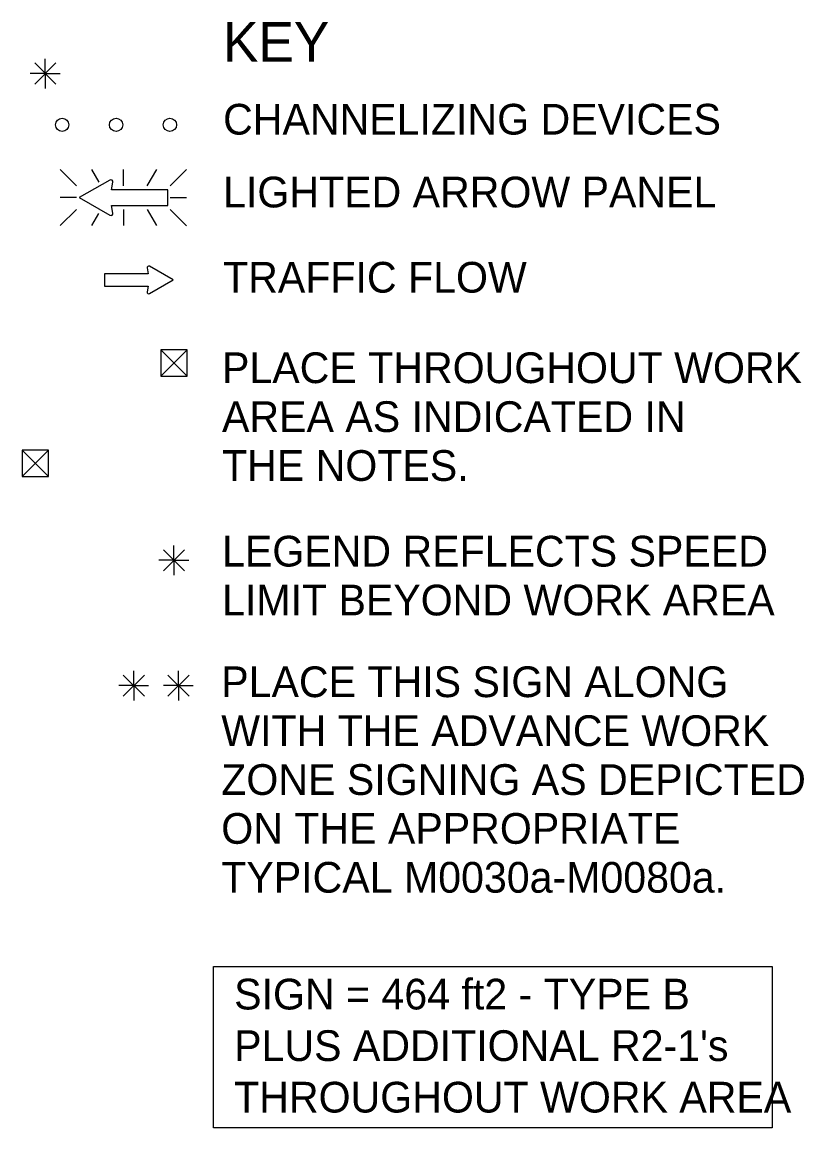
# Model space of a CAD drawing. Extents: x 16480 to 18482, y 7002 to 8333.
# Drawn here: x 17187.3 to 17423.8, y 7874.7 to 8209.5 of the extents above; entities that cross this region are included whole.
import ezdxf

# ---------------------------------------------------------------- set-up
doc = ezdxf.new("R2010")
doc.units = 0
for name, color, linetype in [('MT_SCRATCH_LEVEL_E', 7, 'Continuous'), ('TRAFFIC_SIGNS_PR', 7, 'Continuous'), ('TYPICAL_TEXT_DIMEN_EX', 7, 'Continuous'), ('TYPICAL_TEXT_DIMEN_PR', 7, 'Continuous')]:
    doc.layers.add(name, color=color, linetype=linetype)

msp = doc.modelspace()

# ---------------------------------------------------------------- linework, layer by layer
at = {"layer": 'MT_SCRATCH_LEVEL_E'}
for p, q in [((17225.12, 8135.05), (17225.43, 8133.27)), ((17233.04, 8131.42), (17225.8, 8135.53)), ((17225.43, 8133.27), (17212.17, 8133.27)), ((17212.17, 8133.27), (17212.17, 8129.53)), ((17212.17, 8129.53), (17225.43, 8129.53)), ((17225.43, 8129.53), (17225.12, 8127.75)), ((17225.8, 8127.28), (17233.04, 8131.42))]:
    msp.add_line(p, q, dxfattribs=at)
for centre, start, end in [((17225.58, 8135.13), 60.4248, 189.9638), ((17225.58, 8127.69), 170.0362, 299.7731)]:
    msp.add_arc(centre, 0.463, start, end, dxfattribs=at)
at = {"layer": 'TRAFFIC_SIGNS_PR'}
for p, q in [((17198.85, 8164.8), (17203.79, 8159.87)), ((17210.62, 8160.98), (17208.41, 8164.81)), ((17217.94, 8159.87), (17217.94, 8164.81)), ((17225.17, 8159.87), (17228.02, 8164.81)), ((17232.08, 8159.87), (17237.02, 8164.81)), ((17203.79, 8156.32), (17198.85, 8156.32)), ((17232.08, 8156.32), (17237.02, 8156.32)), ((17198.85, 8147.83), (17203.79, 8152.76)), ((17217.94, 8152.76), (17217.94, 8147.83)), ((17228.06, 8147.83), (17225.22, 8152.76)), ((17232.08, 8152.76), (17237.02, 8147.82)), ((17208.36, 8147.83), (17210.48, 8151.49))]:
    msp.add_line(p, q, dxfattribs=at)
for points in [[(17213.86, 8161.59), (17204.57, 8156.32), (17213.87, 8150.99)], [(17214.74, 8151.62), (17214.34, 8153.89), (17231.35, 8153.89), (17231.35, 8158.69), (17214.34, 8158.69), (17214.74, 8160.97)]]:
    msp.add_lwpolyline(points, dxfattribs=at)
for centre in [(17199.42, 8178.35), (17215.72, 8178.35), (17232.02, 8178.35)]:
    msp.add_circle(centre, 2, dxfattribs=at)
for centre, radius, start, end in [((17214.15, 8161.07), 0.598, 350.7308, 118.8916), ((17214.15, 8151.52), 0.597, 241.4833, 9.9593)]:
    msp.add_arc(centre, radius, start, end, dxfattribs=at)
at = {"layer": 'TYPICAL_TEXT_DIMEN_EX'}
msp.add_lwpolyline([(17245.22, 7923.51), (17414.22, 7923.51), (17414.22, 7874.68), (17245.22, 7874.68)], close=True, dxfattribs=at)
at = {"layer": 'TYPICAL_TEXT_DIMEN_PR'}
for p, q in [((17191.11, 8197.08), (17197.49, 8190.7)), ((17197.49, 8197.08), (17191.11, 8190.7)), ((17194.3, 8193.89), (17194.3, 8198.35)), ((17194.3, 8193.89), (17189.77, 8193.89)), ((17194.3, 8193.89), (17197.49, 8193.89)), ((17194.3, 8193.89), (17198.78, 8193.89)), ((17194.3, 8193.89), (17194.3, 8189.39)), ((17229.27, 8110.26), (17237.27, 8102.26)), ((17229.27, 8102.26), (17237.27, 8110.26)), ((17187.29, 8079.87), (17195.29, 8071.87)), ((17187.29, 8071.87), (17195.29, 8079.87)), ((17230.05, 8049.72), (17236.42, 8043.34)), ((17236.42, 8049.72), (17230.05, 8043.34)), ((17233.23, 8046.53), (17233.23, 8050.99)), ((17233.23, 8046.53), (17228.7, 8046.53)), ((17233.23, 8046.53), (17236.42, 8046.53)), ((17233.23, 8046.53), (17237.71, 8046.53)), ((17233.23, 8046.53), (17233.23, 8042.03)), ((17217.91, 8011.77), (17224.28, 8005.4)), ((17224.28, 8011.77), (17217.91, 8005.4)), ((17221.1, 8008.58), (17221.1, 8013.04)), ((17237.79, 8011.77), (17231.41, 8005.4)), ((17231.42, 8011.77), (17237.79, 8005.4)), ((17234.6, 8008.58), (17234.6, 8013.04)), ((17221.1, 8008.58), (17216.56, 8008.58)), ((17221.1, 8008.58), (17224.28, 8008.58)), ((17221.1, 8008.58), (17225.57, 8008.58)), ((17221.1, 8008.58), (17221.1, 8004.08)), ((17234.6, 8008.58), (17230.07, 8008.58)), ((17234.6, 8008.58), (17237.79, 8008.58)), ((17234.6, 8008.58), (17239.08, 8008.58)), ((17234.6, 8008.58), (17234.6, 8004.08))]:
    msp.add_line(p, q, dxfattribs=at)
for points in [[(17229.27, 8110.26), (17229.27, 8102.26), (17237.27, 8102.26), (17237.27, 8110.26)], [(17187.29, 8079.87), (17187.29, 8071.87), (17195.29, 8071.87), (17195.29, 8079.87)]]:
    msp.add_lwpolyline(points, close=True, dxfattribs=at)
msp.add_open_spline([(17326.18, 8047.12), (17326.2, 8047.12), (17326.21, 8047.12), (17326.21, 8047.12)], degree=2, dxfattribs=at)

# ---------------------------------------------------------------- texts
at = {"layer": 'TYPICAL_TEXT_DIMEN_EX'}
for s, height, p in [('KEY', 12, (17248.11, 8197.45)), ('CHANNELIZING DEVICES', 9.3, (17248.11, 8175.4)), ('LIGHTED ARROW PANEL', 9.3, (17248.11, 8153.35)), ('TRAFFIC FLOW', 9.3, (17248.11, 8127.55)), ('PLACE THROUGHOUT WORK', 9.3, (17247.78, 8100.16)), ('AREA AS INDICATED IN ', 9.3, (17247.78, 8085.36)), ('THE NOTES.', 9.3, (17247.78, 8070.56)), ('LEGEND REFLECTS SPEED', 9.3, (17247.79, 8044.63)), ('LIMIT BEYOND WORK AREA', 9.3, (17247.79, 8029.83)), ('PLACE THIS SIGN ALONG', 9.3, (17247.55, 8005.09)), ('WITH THE ADVANCE WORK', 9.3, (17247.55, 7990.29)), ('ZONE SIGNING AS DEPICTED', 9.3, (17247.55, 7975.49)), ('ON THE APPROPRIATE', 9.3, (17247.55, 7960.69)), ('TYPICAL M0030a-M0080a.', 9.3, (17247.55, 7945.89)), ('SIGN = 464 ft2 - TYPE B', 9.3, (17251.45, 7910.53)), ("PLUS ADDITIONAL R2-1's", 9.3, (17251.45, 7894.93)), ('THROUGHOUT WORK AREA', 9.3, (17251.45, 7879.33))]:
    msp.add_text(s, height=height, dxfattribs=at).set_placement(p)

doc.saveas('drawing.dxf')
